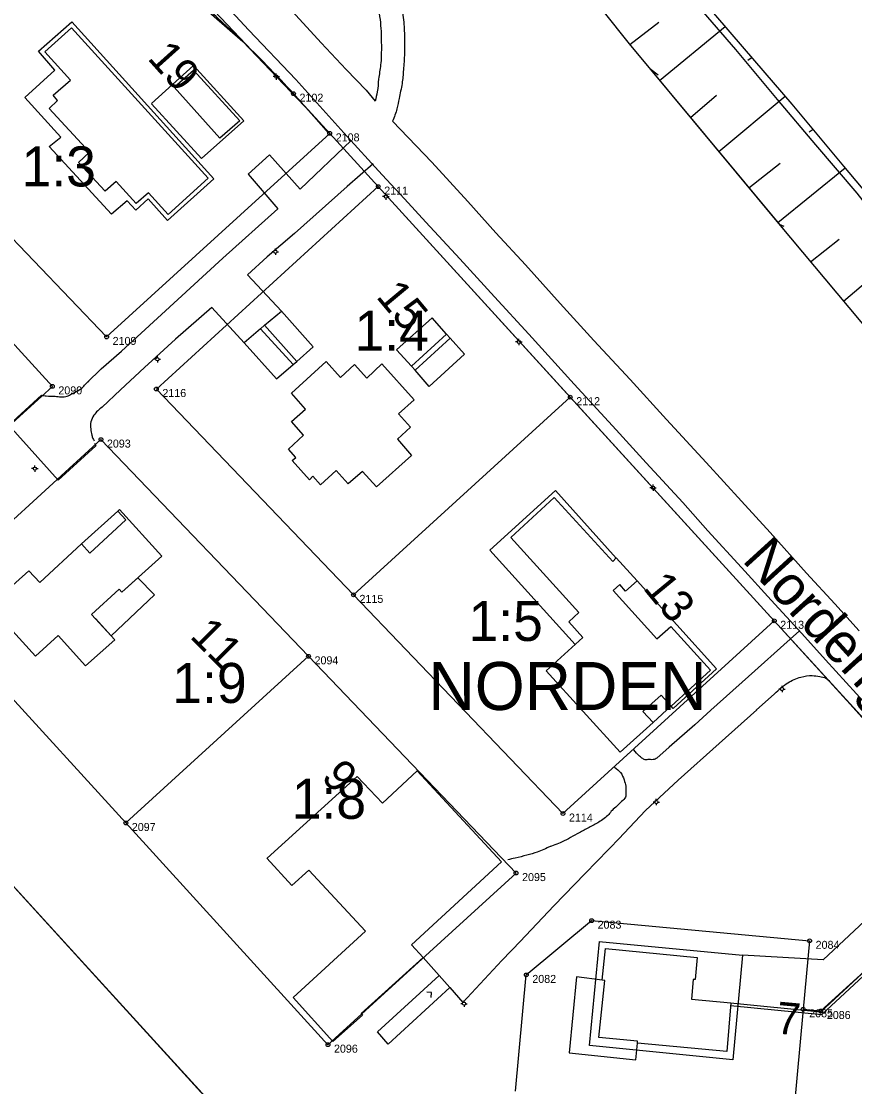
# Model space of a CAD drawing. Extents: x 1517478 to 1518189, y 6494860 to 6495389.
# Drawn here: x 1517979.5 to 1518083.7, y 6495107.4 to 6495240.6 of the extents above; entities that cross this region are included whole.
import ezdxf

# ---------------------------------------------------------------- set-up
doc = ezdxf.new("R2010")
doc.units = 0
for name, color, linetype in [('adress', 7, 'Continuous'), ('altan', 7, 'Continuous'), ('bostadshus', 7, 'Continuous'), ('fastighetsbeteckning', 7, 'Continuous'), ('gatunamn', 7, 'Continuous'), ('gc_vag', 7, 'Continuous'), ('grans', 7, 'Continuous'), ('granspunkt', 7, 'Continuous'), ('granspunkt_text', 7, 'Continuous'), ('kvartersgrans', 7, 'Continuous'), ('kvartersgrans_utan_fastgr', 7, 'Continuous'), ('kvartersnamn', 7, 'Continuous'), ('kvartersytor', 7, 'Continuous'), ('skarmtak', 7, 'Continuous'), ('slant_skraffering', 7, 'Continuous'), ('slantfot', 7, 'Continuous'), ('staket', 7, 'Continuous'), ('stenmur', 7, 'Continuous'), ('stolpe_belysning', 7, 'Continuous'), ('trappa', 7, 'Continuous'), ('trappsymbol', 7, 'Continuous'), ('uthus', 7, 'Continuous'), ('vagkant', 7, 'Continuous')]:
    doc.layers.add(name, color=color, linetype=linetype)

msp = doc.modelspace()

# ---------------------------------------------------------------- linework, layer by layer
at = {"layer": 'altan'}
msp.add_lwpolyline([(1518052.12, 6495120.78), (1518048.93, 6495121.18), (1518048, 6495111.68), (1518056.33, 6495110.79), (1518056.56, 6495112.9)], dxfattribs=at)
at = {"layer": 'bostadshus'}
for points in [[(1517982.48, 6495236.79), (1517985.82, 6495239.79), (1518002.87, 6495221.01), (1517997.88, 6495216.47), (1517995.44, 6495219.18), (1517993.9, 6495217.82), (1517991.38, 6495220.6), (1517989.99, 6495219.38), (1517986.66, 6495222.97), (1517988.07, 6495224.27), (1517983.01, 6495229.73), (1517984.06, 6495230.71), (1517983.52, 6495231.36), (1517985.66, 6495233.27), (1517982.48, 6495236.79)], [(1518013.29, 6495194.12), (1518017.64, 6495198.07), (1518019.42, 6495196.1), (1518021.19, 6495197.7), (1518022.7, 6495196.02), (1518024.6, 6495197.78), (1518028.63, 6495193.3), (1518026.66, 6495191.54), (1518028.19, 6495189.89), (1518026.54, 6495188.39), (1518028.31, 6495186.35), (1518023.92, 6495182.41), (1518022.16, 6495184.36), (1518020.4, 6495182.79), (1518018.9, 6495184.47), (1518016.93, 6495182.68), (1518015.98, 6495183.76), (1518015.54, 6495183.31), (1518013.4, 6495185.71), (1518013.86, 6495186.11), (1518012.94, 6495187.14), (1518014.82, 6495188.89), (1518013.31, 6495190.58), (1518015.04, 6495192.12), (1518013.29, 6495194.12)], [(1518040.73, 6495176.09), (1518046.15, 6495181.08), (1518053.45, 6495173.08), (1518053.89, 6495173.53), (1518056.49, 6495170.67), (1518055.05, 6495169.4), (1518054.35, 6495170.23), (1518053.49, 6495169.48), (1518058.96, 6495163.41), (1518060.7, 6495164.96), (1518065.68, 6495159.49), (1518060.76, 6495155.03), (1518059.49, 6495156.39), (1518057.23, 6495154.36), (1518058.51, 6495152.97), (1518054.38, 6495149.24), (1518045.11, 6495159.41), (1518049.7, 6495163.58), (1518047.96, 6495165.53), (1518049.23, 6495166.71), (1518040.73, 6495176.09)], [(1517975.57, 6495167.55), (1517980.48, 6495171.93), (1517981.83, 6495170.45), (1517987.06, 6495175.28), (1517988.1, 6495174.14), (1517992.61, 6495178.29), (1517991.59, 6495179.38), (1517991.82, 6495179.58), (1517997.11, 6495173.74), (1517992.09, 6495169.26), (1517991.75, 6495169.62), (1517988.32, 6495166.48), (1517991.2, 6495163.3), (1517987.55, 6495160.07), (1517984.13, 6495163.84), (1517981.3, 6495161.27), (1517975.57, 6495167.55)], [(1518010.24, 6495136.01), (1518021.49, 6495146.21), (1518024.66, 6495142.89), (1518028.99, 6495146.91), (1518039.53, 6495135.57), (1518028.29, 6495125.18), (1518029.76, 6495123.58), (1518022.02, 6495116.58), (1518022.18, 6495116.39), (1518018.47, 6495113.08), (1518013.52, 6495118.58), (1518022.53, 6495126.88), (1518015.48, 6495134.51), (1518013.35, 6495132.59), (1518010.23, 6495136.01)], [(1518052.55, 6495124.74), (1518064, 6495123.59), (1518063.75, 6495120.85), (1518063.52, 6495120.86), (1518063.29, 6495118.38), (1518068.2, 6495117.91), (1518067.7, 6495111.84), (1518056.56, 6495112.9), (1518056.56, 6495113.13), (1518051.72, 6495113.61), (1518052.47, 6495120.74), (1518052.12, 6495120.78), (1518052.55, 6495124.74)]]:
    msp.add_lwpolyline(points, dxfattribs=at)
at = {"layer": 'gc_vag'}
msp.add_line((1518071.39, 6495154.52), (1518073.68, 6495156.57), dxfattribs=at)
for points in [[(1518003.63, 6495241.88), (1518003.63, 6495241.91), (1518007.63, 6495237.7), (1518010.48, 6495234.7), (1518013.14, 6495232.03), (1518016.08, 6495228.73), (1518017.93, 6495226.61)], [(1518020.74, 6495225.7), (1518014.37, 6495219.64), (1518010.55, 6495223.93), (1518007.87, 6495221.49), (1518011.61, 6495217.19)], [(1518023.5, 6495222.78), (1518020.24, 6495219.96), (1518013.66, 6495214.09)], [(1518011.61, 6495217.19), (1518004.71, 6495211.01), (1517997.03, 6495203.95)], [(1518013.66, 6495214.09), (1518010.26, 6495211.17), (1518007.82, 6495208.93), (1518012.07, 6495204.4)], [(1518007.39, 6495200.41), (1518003.36, 6495204.82), (1517998.81, 6495200.9), (1517994.94, 6495197.32)], [(1517987.77, 6495195.46), (1517989.52, 6495197.19), (1517992.05, 6495199.37), (1517994.02, 6495201.19), (1517997.03, 6495203.95)], [(1517994.94, 6495197.32), (1517991.91, 6495194.55), (1517989.62, 6495192.39)], [(1517988.68, 6495187.89), (1517988.86, 6495187.55), (1517984.15, 6495183.26), (1517977.97, 6495190.13), (1517982.05, 6495193.87)], [(1518076.79, 6495164.43), (1518075.63, 6495163.38), (1518070.4, 6495158.71), (1518065.72, 6495154.49), (1518063.7, 6495152.67)], [(1518080.55, 6495158.09), (1518082.73, 6495155.72), (1518085.02, 6495153.19)], [(1518054.23, 6495138.43), (1518057.55, 6495141.96), (1518061.62, 6495145.76), (1518066.75, 6495150.35), (1518071.45, 6495154.57)], [(1518063.7, 6495152.67), (1518060.52, 6495149.87), (1518058.98, 6495148.51)], [(1518097.3, 6495139.7), (1518079.77, 6495123.29), (1518069.67, 6495123.88)], [(1518041.89, 6495125.55), (1518041.87, 6495125.6), (1518046.09, 6495130.04), (1518050.01, 6495134.11), (1518054.38, 6495138.58)], [(1518033.07, 6495119.83), (1518034.72, 6495117.97), (1518039.6, 6495123.22), (1518041.95, 6495125.7)]]:
    msp.add_lwpolyline(points, dxfattribs=at)
for points in [[(1518025.84, 6495247.94), (1518026.48, 6495245.38), (1518026.99, 6495242.87), (1518027.33, 6495240.49), (1518027.42, 6495238.32), (1518027.42, 6495236.58), (1518027.29, 6495234.53), (1518027.12, 6495232.83), (1518026.74, 6495230.96), (1518026.48, 6495229.68), (1518025.93, 6495228.11)], [(1518024.04, 6495243.13), (1518024.44, 6495240.07), (1518024.53, 6495237.26), (1518024.44, 6495235.17), (1518024.19, 6495233.39), (1518024.02, 6495231.81), (1518023.76, 6495230.62)], [(1517982.05, 6495193.87), (1517982.65, 6495193.79), (1517983.76, 6495193.74), (1517984.49, 6495193.68), (1517985.26, 6495193.76), (1517985.81, 6495194.03), (1517986.39, 6495194.34), (1517987.1, 6495194.76), (1517987.55, 6495195.26), (1517987.97, 6495195.63)], [(1517989.62, 6495192.39), (1517988.6, 6495191.37), (1517988.23, 6495190.55), (1517988.2, 6495189.68), (1517988.34, 6495188.87), (1517988.47, 6495188.47), (1517988.62, 6495188.18)], [(1518073.68, 6495156.57), (1518075.34, 6495157.93), (1518076.97, 6495158.65), (1518078.39, 6495158.83), (1518079.32, 6495158.71), (1518080.08, 6495158.5), (1518080.56, 6495158.08)], [(1518058.98, 6495148.51), (1518058.5, 6495148.33), (1518057.83, 6495148.33), (1518057.38, 6495148.33), (1518057.2, 6495148.45), (1518056.81, 6495148.75), (1518056.08, 6495149.57)], [(1518053.66, 6495147.39), (1518054.44, 6495146.7), (1518054.86, 6495145.8), (1518055.07, 6495145.01), (1518055.1, 6495144.2), (1518055.04, 6495143.65), (1518054.56, 6495143.11), (1518053.99, 6495142.54), (1518053.38, 6495141.99), (1518052.96, 6495141.48), (1518052.39, 6495140.97), (1518051.73, 6495140.51), (1518050.49, 6495139.85), (1518049.25, 6495139.19), (1518047.11, 6495138.04), (1518045.33, 6495137.35)], [(1518045.64, 6495137.47), (1518044.02, 6495136.77), (1518042.72, 6495136.38), (1518041.25, 6495136.02), (1518040.34, 6495135.81)]]:
    msp.add_spline(points, degree=3, dxfattribs=at)
at = {"layer": 'grans'}
for p, q in [((1518018.08, 6495226.6), (1518013.55, 6495231.56)), ((1517962.44, 6495230.13), (1517990.19, 6495201.16)), ((1517990.19, 6495201.16), (1518018.08, 6495226.6)), ((1517960.84, 6495219.72), (1517983.41, 6495194.98)), ((1517996.41, 6495194.65), (1518024.14, 6495219.95)), ((1518024.14, 6495219.95), (1518048.14, 6495193.63)), ((1517983.41, 6495194.98), (1517961.25, 6495174.76)), ((1518021.05, 6495168.92), (1517996.41, 6495194.65)), ((1518048.14, 6495193.63), (1518021.05, 6495168.92)), ((1518073.64, 6495165.68), (1518048.14, 6495193.63)), ((1517967.32, 6495168.11), (1517989.48, 6495188.33)), ((1517989.48, 6495188.33), (1518015.43, 6495161.24)), ((1518021.05, 6495168.92), (1518047.23, 6495141.59)), ((1517992.59, 6495140.41), (1517967.32, 6495168.11)), ((1518047.23, 6495141.59), (1518073.64, 6495165.68)), ((1518015.43, 6495161.24), (1517992.59, 6495140.41)), ((1518041.37, 6495134.15), (1518015.43, 6495161.24)), ((1517992.59, 6495140.41), (1518017.86, 6495112.7)), ((1518017.86, 6495112.7), (1518041.37, 6495134.15)), ((1518079.46, 6495116.91), (1518095.04, 6495131.13)), ((1518042.65, 6495121.42), (1518050.81, 6495128.2)), ((1518050.81, 6495128.2), (1518078.06, 6495125.68)), ((1518078.06, 6495125.68), (1518077.26, 6495117.12)), ((1518041.31, 6495106.88), (1518042.65, 6495121.42)), ((1518077.26, 6495117.12), (1518075.29, 6495095.71)), ((1518077.26, 6495117.12), (1518079.46, 6495116.91))]:
    msp.add_line(p, q, dxfattribs=at)
msp.add_arc((1517907.57, 6495134.85), 143.47, 42.3829, 49.656, dxfattribs=at)
at = {"layer": 'granspunkt'}
for centre in [(1518013.55, 6495231.56), (1518018.08, 6495226.6), (1518024.14, 6495219.95), (1517990.19, 6495201.16), (1517983.41, 6495194.98), (1517996.41, 6495194.65), (1518048.14, 6495193.63), (1517989.48, 6495188.33), (1518021.05, 6495168.92), (1518073.64, 6495165.68), (1518015.43, 6495161.24), (1518047.23, 6495141.59), (1517992.59, 6495140.41), (1518041.37, 6495134.15), (1518050.81, 6495128.2), (1518078.06, 6495125.68), (1518042.65, 6495121.42), (1518077.26, 6495117.12), (1518079.46, 6495116.91), (1518017.86, 6495112.7)]:
    msp.add_circle(centre, 0.237, dxfattribs=at)
at = {"layer": 'kvartersgrans'}
msp.add_line((1518013.55, 6495231.56), (1518018.08, 6495226.6), dxfattribs=at)
msp.add_lwpolyline([(1518024.14, 6495219.95), (1518048.14, 6495193.63), (1518073.64, 6495165.68)], dxfattribs=at)
msp.add_arc((1517907.58, 6495134.86), 143.46, 42.3826, 49.6563, dxfattribs=at)
at = {"layer": 'kvartersgrans_utan_fastgr'}
for p, q in [((1518018.08, 6495226.6), (1518024.14, 6495219.95)), ((1517921.04, 6495195.52), (1518074.11, 6495027.69)), ((1518073.64, 6495165.68), (1518099.97, 6495136.82))]:
    msp.add_line(p, q, dxfattribs=at)
at = {"layer": 'kvartersytor'}
msp.add_lwpolyline([(1518074.11, 6495027.69), (1517921.04, 6495195.52), (1517981.66, 6495246.18), (1517987.04, 6495250.68), (1517987.4, 6495250.96), (1517987.81, 6495251.2), (1517988.26, 6495251.41), (1517988.58, 6495251.53), (1517989.03, 6495251.64), (1517989.55, 6495251.72), (1517989.95, 6495251.73), (1517990.42, 6495251.71), (1517990.85, 6495251.63), (1517991.35, 6495251.5), (1517991.85, 6495251.31), (1517992.28, 6495251.07), (1517992.57, 6495250.87), (1517992.84, 6495250.66), (1518007.2, 6495238.09), (1518015.81, 6495229.08), (1518018.08, 6495226.6), (1518024.14, 6495219.95), (1518073.64, 6495165.68), (1518099.97, 6495136.82)], dxfattribs=at)
at = {"layer": 'skarmtak'}
for p, q in [((1517981.67, 6495236.86), (1517985.85, 6495240.55)), ((1518046.29, 6495181.97), (1518053.9, 6495173.52)), ((1517987.06, 6495175.28), (1517991.59, 6495179.38)), ((1518060.76, 6495155.04), (1518058.51, 6495152.98))]:
    msp.add_line(p, q, dxfattribs=at)
for points in [[(1517985.85, 6495240.55), (1518003.59, 6495220.94), (1517997.81, 6495215.72), (1517995.37, 6495218.42), (1517993.84, 6495217.02), (1517992.75, 6495218.17), (1517990.81, 6495216.49), (1517983.03, 6495224.95), (1517984.48, 6495226.14), (1517979.97, 6495231.08), (1517983.72, 6495234.49), (1517981.67, 6495236.86)], [(1517995.8, 6495230.34), (1518001.07, 6495235.1), (1518007.33, 6495228.18), (1518002.07, 6495223.45), (1517995.79, 6495230.31)], [(1518009.92, 6495202.64), (1518012.07, 6495204.4), (1518016.01, 6495199.93), (1518013.98, 6495198.1)], [(1518032.66, 6495201.51), (1518030.87, 6495203.55), (1518026.44, 6495199.54), (1518028.31, 6495197.52)], [(1518009.41, 6495202.19), (1518007.39, 6495200.41), (1518011.44, 6495195.92), (1518013.51, 6495197.71)], [(1518033.12, 6495201.01), (1518034.94, 6495199.02), (1518030.51, 6495194.97), (1518028.77, 6495197.02)], [(1518048.74, 6495162.7), (1518038.11, 6495174.52), (1518046.3, 6495181.97)], [(1517988.32, 6495166.48), (1517991.75, 6495169.62), (1517992.09, 6495169.26), (1517994.1, 6495171.06), (1517996.19, 6495168.92), (1517990.75, 6495163.8), (1517988.79, 6495165.96)], [(1518056.49, 6495170.68), (1518066.41, 6495159.66), (1518061.02, 6495154.73), (1518060.76, 6495155.03)], [(1518051.75, 6495125.58), (1518069.67, 6495123.88), (1518068.46, 6495110.79), (1518050.53, 6495112.59), (1518051.78, 6495125.58)]]:
    msp.add_lwpolyline(points, dxfattribs=at)
at = {"layer": 'slant_skraffering'}
for p, q in [((1518055.6, 6495237.7), (1518059.22, 6495240.5)), ((1518059.31, 6495233.23), (1518067.52, 6495239.96)), ((1518070.86, 6495236.08), (1518070.32, 6495235.7)), ((1518058.07, 6495234.72), (1518059.14, 6495233.93)), ((1518063.19, 6495228.57), (1518066.41, 6495231.37)), ((1518066.72, 6495224.32), (1518075, 6495231.26)), ((1518078.5, 6495227.09), (1518078.01, 6495226.76)), ((1518070.48, 6495219.79), (1518074.39, 6495222.87)), ((1518074.07, 6495215.46), (1518082.52, 6495222.28)), ((1518078.17, 6495210.56), (1518081.75, 6495213.39)), ((1518082.3, 6495205.63), (1518090.55, 6495212.65))]:
    msp.add_line(p, q, dxfattribs=at)
at = {"layer": 'slantfot'}
for points in [[(1518074.04, 6495230.84), (1518068.84, 6495237.08), (1518064.02, 6495242.66), (1518058.2, 6495249.4)], [(1518092.27, 6495208.77), (1518088.68, 6495213.17), (1518084, 6495219.13), (1518078.82, 6495225.16), (1518074.04, 6495230.84)]]:
    msp.add_lwpolyline(points, dxfattribs=at)
at = {"layer": 'staket'}
for p, q in [((1518055.52, 6495237.8), (1518074.17, 6495215.34)), ((1518055.52, 6495237.8), (1518074.7, 6495214.71)), ((1518029.76, 6495123.58), (1518031.76, 6495121.35))]:
    msp.add_line(p, q, dxfattribs=at)
for points in [[(1518041.26, 6495255.67), (1518042.34, 6495254.35), (1518055.52, 6495237.8)], [(1518055.52, 6495237.8), (1518074.24, 6495215.26), (1518074.24, 6495215.26), (1518074.83, 6495215.01)], [(1518074.17, 6495215.34), (1518084.47, 6495203.04), (1518092.38, 6495193.53)]]:
    msp.add_lwpolyline(points, dxfattribs=at)
at = {"layer": 'stenmur'}
for p, q in [((1518009.41, 6495202.19), (1518009.92, 6495202.64)), ((1518013.51, 6495197.71), (1518009.41, 6495202.19)), ((1518013.98, 6495198.1), (1518009.92, 6495202.64)), ((1518028.31, 6495197.52), (1518032.66, 6495201.51)), ((1518028.77, 6495197.02), (1518033.12, 6495201.01)), ((1518032.66, 6495201.51), (1518033.12, 6495201.01)), ((1518013.51, 6495197.71), (1518013.98, 6495198.1)), ((1518013.56, 6495197.67), (1518013.56, 6495197.67)), ((1518028.31, 6495197.52), (1518028.77, 6495197.02))]:
    msp.add_line(p, q, dxfattribs=at)
for points in [[(1518068.15, 6495117.91), (1518079.47, 6495116.8), (1518086.88, 6495123.66)], [(1518068.17, 6495117.6), (1518079.57, 6495116.49), (1518087.08, 6495123.44)]]:
    msp.add_lwpolyline(points, dxfattribs=at)
at = {"layer": 'stolpe_belysning'}
for p, q in [((1518011.4, 6495233.9), (1518011.4, 6495234.1)), ((1518011.2, 6495233.7), (1518011, 6495233.7)), ((1518011.4, 6495233.5), (1518011.4, 6495233.3)), ((1518011.6, 6495233.7), (1518011.8, 6495233.7)), ((1518024.89, 6495218.7), (1518024.69, 6495218.7)), ((1518025.09, 6495218.9), (1518025.09, 6495219.1)), ((1518025.09, 6495218.5), (1518025.09, 6495218.3)), ((1518025.29, 6495218.7), (1518025.49, 6495218.7)), ((1518011.08, 6495211.8), (1518010.88, 6495211.8)), ((1518011.28, 6495212), (1518011.28, 6495212.2)), ((1518011.28, 6495211.6), (1518011.28, 6495211.4)), ((1518011.48, 6495211.8), (1518011.68, 6495211.8)), ((1518041.71, 6495200.73), (1518041.71, 6495200.93)), ((1518041.51, 6495200.53), (1518041.31, 6495200.53)), ((1518041.71, 6495200.33), (1518041.71, 6495200.13)), ((1518041.91, 6495200.53), (1518042.11, 6495200.53)), ((1517996.33, 6495198.37), (1517996.13, 6495198.37)), ((1517996.53, 6495198.57), (1517996.53, 6495198.77)), ((1517996.53, 6495198.17), (1517996.53, 6495197.97)), ((1517996.73, 6495198.37), (1517996.93, 6495198.37)), ((1517981.02, 6495184.7), (1517980.82, 6495184.7)), ((1517981.22, 6495184.9), (1517981.22, 6495185.1)), ((1517981.42, 6495184.7), (1517981.62, 6495184.7)), ((1517981.22, 6495184.5), (1517981.22, 6495184.3)), ((1518058.3, 6495182.31), (1518058.1, 6495182.31)), ((1518058.5, 6495182.51), (1518058.5, 6495182.71)), ((1518058.5, 6495182.11), (1518058.5, 6495181.91)), ((1518058.7, 6495182.31), (1518058.9, 6495182.31)), ((1518074.41, 6495157.14), (1518074.21, 6495157.14)), ((1518074.61, 6495157.34), (1518074.61, 6495157.54)), ((1518074.61, 6495156.94), (1518074.61, 6495156.74)), ((1518074.81, 6495157.14), (1518075.01, 6495157.14)), ((1518058.9, 6495143.22), (1518058.9, 6495143.42)), ((1518058.7, 6495143.02), (1518058.5, 6495143.02)), ((1518058.9, 6495142.82), (1518058.9, 6495142.62)), ((1518059.1, 6495143.02), (1518059.3, 6495143.02)), ((1518034.87, 6495118.02), (1518034.87, 6495118.22)), ((1518034.67, 6495117.82), (1518034.47, 6495117.82)), ((1518034.87, 6495117.62), (1518034.87, 6495117.42)), ((1518035.07, 6495117.82), (1518035.27, 6495117.82))]:
    msp.add_line(p, q, dxfattribs=at)
for centre in [(1518011.4, 6495233.7), (1518025.09, 6495218.7), (1518011.28, 6495211.8), (1518041.71, 6495200.53), (1517996.53, 6495198.37), (1517981.22, 6495184.7), (1518058.5, 6495182.31), (1518074.61, 6495157.14), (1518058.9, 6495143.02), (1518034.87, 6495117.82)]:
    msp.add_circle(centre, 0.2, dxfattribs=at)
at = {"layer": 'trappa'}
msp.add_lwpolyline([(1518031.76, 6495121.35), (1518033.09, 6495119.84), (1518025.37, 6495112.78), (1518024.04, 6495114.29), (1518031.76, 6495121.35)], dxfattribs=at)
at = {"layer": 'trappsymbol'}
msp.add_lwpolyline([(1518030.76, 6495118.61), (1518030.8, 6495119.21), (1518030.2, 6495119.25)], dxfattribs=at)
at = {"layer": 'uthus'}
msp.add_lwpolyline([(1517998.64, 6495232.38), (1518001.04, 6495234.52), (1518006.85, 6495228.15), (1518004.33, 6495226.02), (1517998.64, 6495232.38)], dxfattribs=at)
at = {"layer": 'vagkant'}
for points in [[(1518075.88, 6495230.24), (1518071.22, 6495235.67), (1518064.8, 6495243.12), (1518059.3, 6495249.4)], [(1518010.86, 6495244.63), (1518013.86, 6495241.39), (1518017.01, 6495237.93), (1518020.13, 6495234.6), (1518022.62, 6495232.02), (1518023.76, 6495230.64)], [(1518004.68, 6495243.05), (1518007.95, 6495239.48), (1518013.83, 6495233.35), (1518019.86, 6495226.68)], [(1518094.04, 6495208.38), (1518088.29, 6495215.41), (1518082.34, 6495222.5), (1518075.88, 6495230.24)], [(1518025.94, 6495228.14), (1518030.83, 6495223.01), (1518035.32, 6495218.1), (1518038.86, 6495214.16), (1518042.56, 6495210.16)], [(1518019.86, 6495226.68), (1518024.65, 6495221.44), (1518027.44, 6495218.44), (1518030.07, 6495215.49), (1518034.35, 6495210.92)], [(1518034.35, 6495210.92), (1518038.68, 6495206.19), (1518042.95, 6495201.52), (1518048.65, 6495195.27)], [(1518042.56, 6495210.16), (1518046.86, 6495205.34), (1518051.08, 6495200.73), (1518055.65, 6495195.82)], [(1518048.65, 6495195.27), (1518053.86, 6495189.54), (1518057.65, 6495185.42), (1518062.2, 6495180.45)], [(1518055.65, 6495195.82), (1518060.17, 6495190.85), (1518065.14, 6495185.45), (1518069.53, 6495180.63)], [(1518069.53, 6495180.63), (1518073.11, 6495176.72), (1518077.69, 6495171.65), (1518081.2, 6495167.8), (1518084.26, 6495164.41)], [(1518062.2, 6495180.45), (1518065.35, 6495176.93), (1518069.53, 6495172.35), (1518073.26, 6495168.26), (1518077.08, 6495164.11)], [(1518077.08, 6495164.11), (1518080.05, 6495160.8), (1518085.2, 6495155.13), (1518088.32, 6495151.7), (1518091.63, 6495148.01)]]:
    msp.add_lwpolyline(points, dxfattribs=at)

# ---------------------------------------------------------------- texts
at = {"layer": 'adress'}
for s, rotation, p in [('19', 311.858, (1517995.19, 6495235.94)), ('15', 309.7861, (1518023.77, 6495206.17)), ('13', 309.455, (1518057.15, 6495169.74)), ('11', 314.9833, (1518000.46, 6495163.66)), ('9', 311.9627, (1518016.89, 6495146.07)), ('7', 354.8003, (1518073.76, 6495114.11))]:
    msp.add_text(s, height=4, rotation=rotation, dxfattribs=at).set_placement(p)
at = {"layer": 'fastighetsbeteckning'}
for s, p in [('1:3', (1517979.56, 6495219.97)), ('1:4', (1518021.17, 6495199.43)), ('1:5', (1518035.42, 6495163.16)), ('1:9', (1517998.4, 6495155.41)), ('1:8', (1518013.33, 6495140.93))]:
    msp.add_text(s, height=5, rotation=0.0021, dxfattribs=at).set_placement(p)
at = {"layer": 'gatunamn'}
msp.add_text('Nordengatan', height=5, rotation=312.3013, dxfattribs=at).set_placement((1518069.51, 6495173.2))
at = {"layer": 'granspunkt_text'}
for s, p in [('2102', (1518014.3, 6495230.56)), ('2108', (1518018.83, 6495225.6)), ('2111', (1518024.89, 6495218.95)), ('2109', (1517990.94, 6495200.16)), ('2090', (1517984.16, 6495193.98)), ('2116', (1517997.16, 6495193.65)), ('2112', (1518048.89, 6495192.63)), ('2093', (1517990.23, 6495187.33)), ('2115', (1518021.8, 6495167.92)), ('2113', (1518074.39, 6495164.68)), ('2094', (1518016.18, 6495160.24)), ('2114', (1518047.98, 6495140.59)), ('2097', (1517993.34, 6495139.41)), ('2095', (1518042.12, 6495133.15)), ('2083', (1518051.56, 6495127.2)), ('2084', (1518078.81, 6495124.68)), ('2082', (1518043.4, 6495120.42)), ('2085', (1518078.01, 6495116.12)), ('2086', (1518080.21, 6495115.91)), ('2096', (1518018.61, 6495111.7))]:
    msp.add_text(s, height=1, dxfattribs=at).set_placement(p)
at = {"layer": 'kvartersnamn'}
msp.add_text('NORDEN', height=6, rotation=0.0021, dxfattribs=at).set_placement((1518030.41, 6495154.53))

doc.saveas('drawing.dxf')
